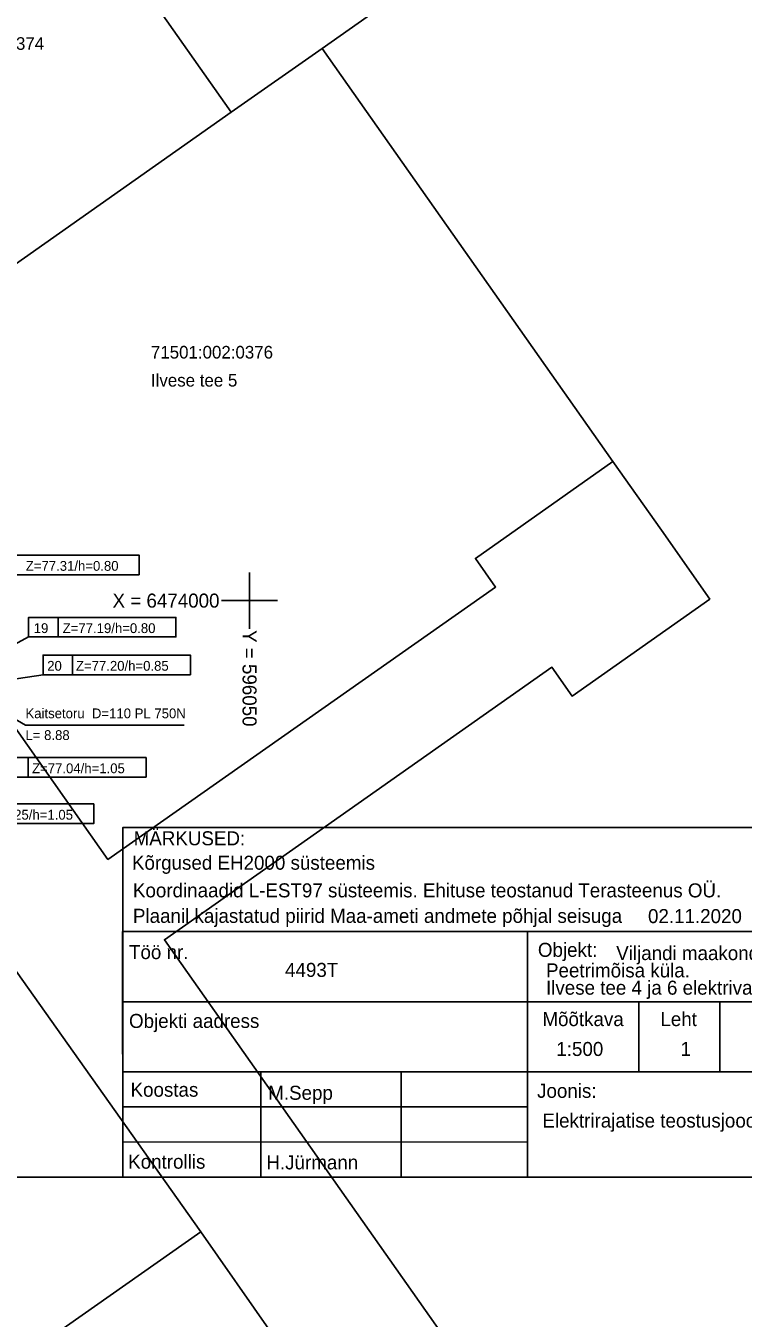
# Model space of a CAD drawing. Extents: x 593727 to 603084, y 6472047 to 6482364.
# Drawn here: x 596034.1 to 596085.2, y 6473948.9 to 6474041 of the extents above; entities that cross this region are included whole.
import ezdxf

# ---------------------------------------------------------------- set-up
doc = ezdxf.new("R2010")
doc.units = 0
for name, color, linetype in [('KOORDPUNKT', 7, 'Continuous'), ('MPKAABEL', 7, 'Continuous'), ('PIIR', 7, 'Continuous'), ('VORK', 7, 'Continuous'), ('VORMISTUS', 7, 'Continuous')]:
    doc.layers.add(name, color=color, linetype=linetype)

msp = doc.modelspace()

# ---------------------------------------------------------------- linework, layer by layer
at = {"layer": 'KOORDPUNKT'}
for points in [[(596026.978, 6473997.816), (596031.622, 6474001.846), (596042.122, 6474001.846), (596042.122, 6474003.246), (596031.622, 6474003.246), (596031.622, 6474001.846)], [(596029.342, 6473994.732), (596034.252, 6473997.407), (596044.752, 6473997.407), (596044.752, 6473998.807), (596034.252, 6473998.807), (596034.252, 6473997.407)], [(596036.352, 6473997.407), (596036.352, 6473998.807)], [(596029.364, 6473993.819), (596035.283, 6473994.721), (596045.783, 6473994.721), (596045.783, 6473996.121), (596035.283, 6473996.121), (596035.283, 6473994.721)], [(596037.383, 6473994.721), (596037.383, 6473996.121)], [(596026.896, 6473991.824), (596032.122, 6473987.416), (596042.622, 6473987.416), (596042.622, 6473988.816), (596032.122, 6473988.816), (596032.122, 6473987.416)], [(596022.401, 6473988.312), (596028.392, 6473984.107), (596038.892, 6473984.107), (596038.892, 6473985.507), (596028.392, 6473985.507), (596028.392, 6473984.107)], [(596034.222, 6473987.416), (596034.222, 6473988.816)]]:
    msp.add_lwpolyline(points, dxfattribs=at)
at = {"layer": 'MPKAABEL'}
msp.add_lwpolyline([(596029.364, 6473993.819), (596034.033, 6473991.113), (596045.337, 6473991.113)], dxfattribs=at)
at = {"layer": 'PIIR'}
for points in [[(596023.26, 6474070.93), (596041.9, 6474084.06), (596046.92, 6474087.6), (596079.95, 6474056.82), (596055.18, 6474039.36), (596048.7, 6474034.81)], [(596017.77, 6474013.02), (595999.85, 6474038.49), (595999.81, 6474054.43), (596023.26, 6474070.93), (596048.7, 6474034.81)], [(596017.77, 6474013.02), (596048.7, 6474034.81), (596055.18, 6474039.36), (596075.89, 6474009.92), (596066.09, 6474003.01), (596067.53, 6474000.96), (596039.91, 6473981.55)], [(595994.75, 6473964.97), (596004.56, 6473971.88), (596003.14, 6473973.91), (596023.13, 6473988.02), (596046.52, 6473955.01), (596016.68, 6473934.04)]]:
    msp.add_lwpolyline(points, close=True, dxfattribs=at)
for points in [[(596066.57, 6473926.31), (596046.52, 6473955.01), (596023.13, 6473988.02), (596003.14, 6473973.91), (596004.56, 6473971.88), (595994.75, 6473964.97), (595991.31, 6473969.86), (595987.85, 6473974.77), (595997.67, 6473981.68), (595999.1, 6473979.65), (596019.09, 6473993.75), (595995.81, 6474026.85), (595974.94, 6474056.4)], [(595999.81, 6474054.43), (595999.85, 6474038.49), (596017.77, 6474013.02), (596039.91, 6473981.55), (596067.53, 6474000.96), (596066.09, 6474003.01), (596075.89, 6474009.92), (596079.35, 6474005.02), (596082.79, 6474000.11), (596072.98, 6473993.2), (596071.55, 6473995.25), (596043.93, 6473975.83), (596066.1, 6473944.35)]]:
    msp.add_lwpolyline(points, dxfattribs=at)
at = {"layer": 'VORK'}
for p, q in [((596050, 6474002), (596050, 6473998)), ((596048, 6474000), (596052, 6474000))]:
    msp.add_line(p, q, dxfattribs=at)
at = {"layer": 'VORMISTUS'}
for p, q in [((596040.953, 6473976.408), (596133.145, 6473976.408)), ((596040.953, 6473976.408), (596040.959, 6473958.907)), ((596069.797, 6473976.397), (596069.799, 6473958.906)), ((596040.954, 6473971.412), (596108.304, 6473971.405)), ((596077.741, 6473971.43), (596077.74, 6473966.431)), ((596083.513, 6473971.429), (596083.512, 6473966.43)), ((596040.957, 6473966.406), (596108.305, 6473966.406)), ((596050.802, 6473966.406), (596050.805, 6473958.906)), ((596060.806, 6473966.406), (596060.807, 6473958.91)), ((596040.956, 6473963.913), (596069.799, 6473963.907)), ((596040.957, 6473961.41), (596069.799, 6473961.412)), ((596040.959, 6473958.907), (596133.145, 6473958.907))]:
    msp.add_line(p, q, dxfattribs=at)
for points in [[(595935.65, 6473958.907), (595935.65, 6474102.407), (596133.15, 6474102.407), (596133.15, 6473958.907)], [(596131.906, 6473958.907), (596040.959, 6473958.907), (596040.959, 6473983.816), (596131.906, 6473983.816)]]:
    msp.add_lwpolyline(points, close=True, dxfattribs=at)
msp.add_lwpolyline([(596040.959, 6473958.907), (596133.145, 6473958.907)], dxfattribs=at)

# ---------------------------------------------------------------- texts
at = {"layer": 'KOORDPUNKT'}
for s, p in [('Z=77.31/h=0.80', (596034.055, 6474002.126)), ('19', (596034.62, 6473997.687)), ('Z=77.19/h=0.80', (596036.685, 6473997.687)), ('20', (596035.581, 6473995.001)), ('Z=77.20/h=0.85', (596037.629, 6473995.001)), ('Z=77.04/h=1.05', (596034.502, 6473987.696)), ('Z=77.25/h=1.05', (596030.807, 6473984.387))]:
    msp.add_text(s, height=0.7, dxfattribs=at).set_placement(p)
at = {"layer": 'MPKAABEL'}
for s, p in [('Kaitsetoru  D=110 PL 750N', (596034.033, 6473991.613)), ('L= 8.88', (596034.033, 6473990.063))]:
    msp.add_text(s, height=0.7, dxfattribs=at).set_placement(p)
at = {"layer": 'PIIR'}
for s, p in [('71501:002:0374', (596026.662, 6474039.259)), ('71501:002:0376', (596042.972, 6474017.255)), ('Ilvese tee 5', (596042.972, 6474015.255))]:
    msp.add_text(s, height=0.9, dxfattribs=at).set_placement(p)
at = {"layer": 'VORK'}
msp.add_text('X = 6474000', height=1, dxfattribs=at).set_placement((596040.236, 6473999.5))
msp.add_text('Y = 596050 ', height=1, rotation=270, dxfattribs=at).set_placement((596049.5, 6473997.9))
at = {"layer": 'VORMISTUS'}
for s, height, rotation, p in [('MÄRKUSED:', 1, 359.99461, (596041.74, 6473982.559)), ('Kõrgused EH2000 süsteemis', 1.00002, 359.99461, (596041.62, 6473980.819)), ('Koordinaadid L-EST97 süsteemis. Ehituse teostanud Terasteenus OÜ.', 0.99996, 359.99461, (596041.69, 6473978.849)), ('Plaanil kajastatud piirid Maa-ameti andmete põhjal seisuga', 0.99996, 359.99461, (596041.69, 6473977.032)), ('02.11.2020', 0.9997, 359.99742, (596078.394, 6473977.013)), ('Töö nr.', 0.9997, 359.99742, (596041.41, 6473974.448)), ('Objekt:', 0.9997, 359.99742, (596070.548, 6473974.608)), ('Viljandi maakond, Viljandi vald,', 0.99972, 359.99742, (596076.128, 6473974.377)), ('4493T', 0.9997, 359.99742, (596052.53, 6473973.178)), ('Peetrimõisa küla.', 0.99972, 359.99742, (596071.126, 6473973.144)), ('Ilvese tee 4 ja 6 elektrivarustus', 0.99972, 359.99742, (596071.126, 6473971.911)), ('Objekti aadress', 0.99966, 359.99742, (596041.41, 6473969.54)), ('Mõõtkava', 0.9997, 359.99742, (596070.869, 6473969.672)), ('Leht', 0.9997, 359.99742, (596079.278, 6473969.672)), ('1:500', 0.9997, 359.99742, (596071.862, 6473967.542)), ('1', 1, 359.99742, (596080.708, 6473967.542)), ('Koostas', 0.9997, 359.99742, (596041.52, 6473964.638)), ('M.Sepp', 0.9997, 359.99742, (596051.33, 6473964.418)), ('Joonis:', 0.9997, 359.99742, (596070.491, 6473964.558)), ('Elektrirajatise teostusjooonis', 0.99972, 359.99742, (596070.871, 6473962.438)), (' Kontrollis', 0.99966, 359.99742, (596040.98, 6473959.508)), ('H.Jürmann', 1, 359.99742, (596051.2, 6473959.458))]:
    msp.add_text(s, height=height, rotation=rotation, dxfattribs=at).set_placement(p)

doc.saveas('drawing.dxf')
